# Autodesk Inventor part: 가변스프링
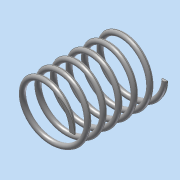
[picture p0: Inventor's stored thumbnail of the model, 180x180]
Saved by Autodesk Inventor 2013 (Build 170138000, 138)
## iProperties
Created: 2018-06
Part Number: 가변스프링
Material: 강철, 연강
Document SubType Name: Modeling
Designer: Administrator
Density: 7.86 g/cm^3
Mass: 82.8071 g
Surface Area: 106.473 cm^2
Volume: 10.5353 cm^3
Author: Administrator
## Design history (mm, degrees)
sketch "스케치1"
  geometry: L1 (0, 0)-(22.5, 0); L2 (0, 0)-(0, 73.25); L3 (0, 73.25)-(22.5, 73.25); C1 r 2 at (22.5, 0)
  constraints: 6 end point, 2 perpendicular, 1 centre point, 1 coincident, 1 horizontal
  dimensions: "d0" = 22.5 distance of L1.start L1.end; "d1" = 4 diameter of C1; "d2" = 73.25 distance of L1.start L2.end (derived); "d3" = 22.5 distance of L2.end L3.end
feature "코일1" sketch "스케치1" pitch "d4" = 10; turns "d6" = 6; dims "d5" = 73.25 (= d2), "d7" = 0, angle "d8" = 90 deg, angle "d9" = 90 deg, "d10" = 0, "d11" = 0
sketch "스케치2"
  geometry: L1 (0, -25)-(73.25, -25); L2 (73.25, -25)-(73.25, 25); L3 (73.25, 25)-(0, 25); L4 (0, 25)-(0, -25); 2 further points
  constraints: 8 end point, 2 parallel, 1 coincident, 1 horizontal, 1 midpoint, 1 perpendicular
  dimensions: "d12" = 73.25 distance of L2.end L3.end (derived); "d14" = 50 distance of L1.end L2.end
extrude "돌출1" sketch "스케치2" stored distance "d15" = 0; taper "d16" = 0 deg
node "솔리드1"
